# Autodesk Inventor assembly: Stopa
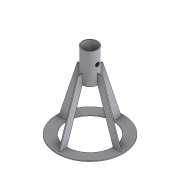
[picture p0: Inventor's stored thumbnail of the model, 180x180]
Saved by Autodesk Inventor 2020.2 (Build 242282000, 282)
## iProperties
Created: 2011-11
Part Number: Stopa
Document SubType Name: Assembly
Designer: F.Stasiak
Catalog Web Link: www.expertbooks.pl
Manager: www.cadconsulting.pl
Company: Fabian Stasiak CAD Consulting
Author: F.Stasiak
Subject: Zbiór ćwiczeń. Autodesk Inventor 2020. Kurs Professional
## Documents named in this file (4)
- C:\2020_Kurs_Professional\R4 MES\Podpora\Stopa.iam
- C:\2020_Kurs_Professional\R4 MES\Podpora\Płyta okrągła.ipt
- C:\2020_Kurs_Professional\R4 MES\Podpora\Rura stopy.ipt
- C:\2020_Kurs_Professional\R4 MES\Podpora\Noga stopy.ipt
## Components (6 placed, 3 different names)
1. Płyta okrągła:1 — Zestawiający:1, Zestawiający:2, Zestawiający:3
2. Rura stopy:1 — Zestawiający:1, Zestawiający:2, Styczny:1
3. Noga stopy:1 — Równoległy:3, Zestawiający:3, Styczny:1
4. Noga stopy:2
5. Noga stopy:3
6. Noga stopy:4
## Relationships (5: Mate 3, Flush 1, Tangent 1)
- Równoległy:3 [Flush]: Noga stopy:1
- Zestawiający:1 [Mate]: Płyta okrągła:1 ↔ Rura stopy:1
- Zestawiający:2 [Mate]: Płyta okrągła:1 ↔ Rura stopy:1
- Zestawiający:3 [Mate]: Płyta okrągła:1 ↔ Noga stopy:1
- Styczny:1 [Tangent]: Rura stopy:1 ↔ Noga stopy:1
